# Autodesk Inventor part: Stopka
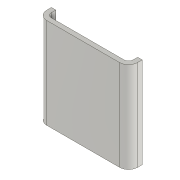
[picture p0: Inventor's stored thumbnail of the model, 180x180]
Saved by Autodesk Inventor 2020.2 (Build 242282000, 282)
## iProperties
Created: 2011-11
Part Number: Stopka
Material: Stal
Document SubType Name: Modeling
Designer: F.Stasiak
Density: 7.85 g/cm^3
Mass: 445.731 g
Surface Area: 248.48 cm^2
Volume: 56.781 cm^3
Appearance: Stal
Catalog Web Link: www.expertbooks.pl
Manager: www.cadconsulting.pl
Company: Fabian Stasiak CAD Consulting
Author: F.Stasiak
Subject: Zbiór ćwiczeń. Autodesk Inventor 2020. Kurs Professional
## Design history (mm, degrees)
sketch "Szkic1"
  geometry: L1 (-50, 0)-(50, 0); L2 (50, 0)-(50, 15); L3 (50, 15)-(45, 15); L4 (45, 15)-(45, 5); L5 (-50, 0)-(-50, 15); L6 (-50, 15)-(-45, 15); L7 (-45, 15)-(-45, 5); L8 (-45, 5)-(45, 5); 2 further points
  constraints: 16 end point, 5 parallel, 2 perpendicular, 1 coincident, 1 collinear, 1 horizontal, 1 midpoint
  dimensions: "d0" = 100 distance of L1.start L1.end; "d1" = 15 distance of L1.end L2.end; "d2" = 5 distance of L2.end L3.end; "d3" = 10 distance of L3.end L4.end; "d5" = 90 distance of L7.end L4.end
extrude "Wyciągnięcie proste1" new body sketch "Szkic1" stored distance "d6" = 100 (= d0); taper "d7" = 0 deg
fillet "Zaokrąglenie1" dims "d8" = 5, "d9" = 10
node "Bryła1"
